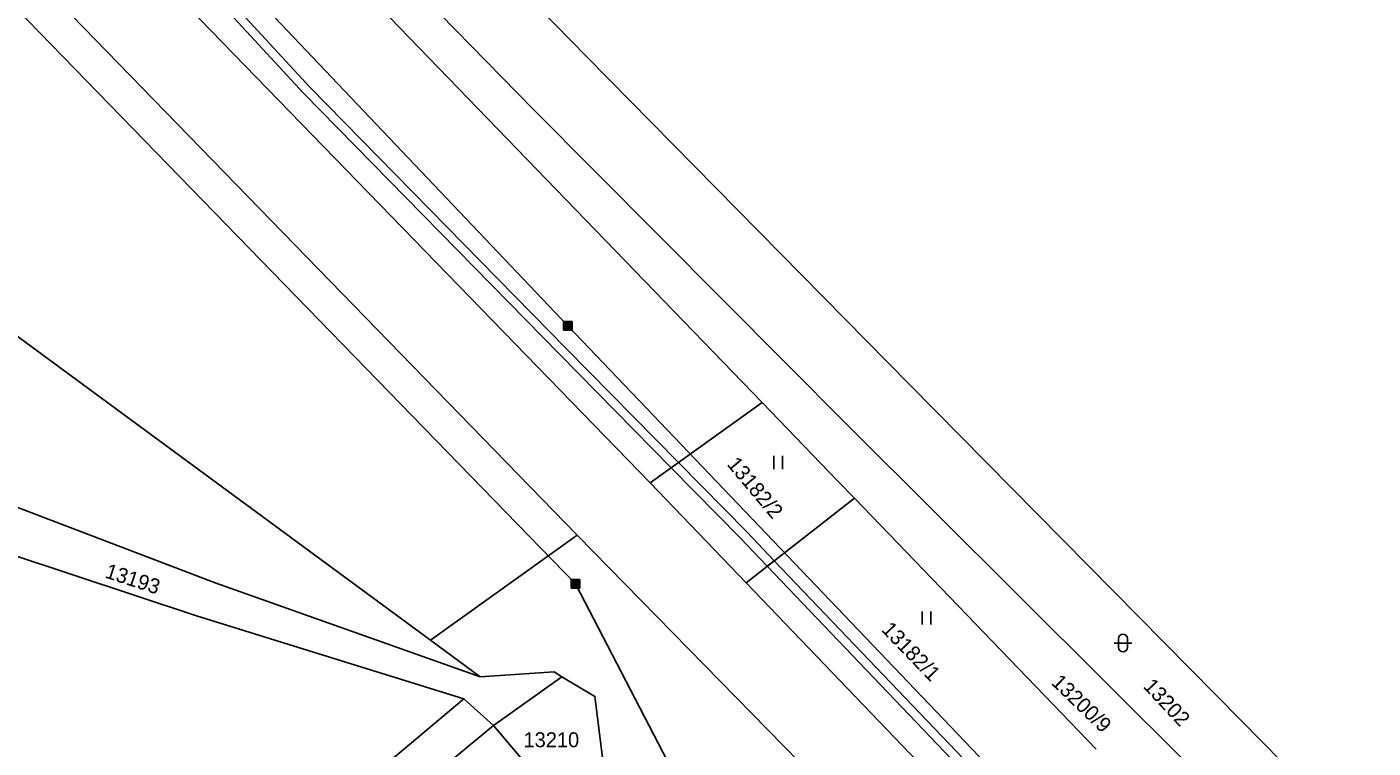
# Model space of a CAD drawing. Extents: x -821458 to -820266, y -1071458 to -1069826.
# Drawn here: x -820498 to -820345.1, y -1071152.4 to -1071070.4 of the extents above; entities that cross this region are included whole.
import ezdxf

# ---------------------------------------------------------------- set-up
doc = ezdxf.new("R2010")
doc.units = 0
for name, color, linetype in [('Vrstva 1', 7, 'Continuous'), ('Vrstva 13', 7, 'Continuous'), ('Vrstva 2', 7, 'Continuous'), ('Vrstva 3', 7, 'Continuous'), ('Vrstva 6', 7, 'Continuous')]:
    doc.layers.add(name, color=color, linetype=linetype)

msp = doc.modelspace()

# ---------------------------------------------------------------- linework, layer by layer
at = {"layer": 'Vrstva 1'}
for p, q in [((-820414.5, -1071113.1), (-820488.98, -1071036.1)), ((-820414.5, -1071113.1), (-820427.22, -1071122.22)), ((-820405.94, -1071121.99), (-820414.5, -1071113.1)), ((-820427.22, -1071122.22), (-820416.32, -1071133.58)), ((-820404.04, -1071123.96), (-820405.94, -1071121.99)), ((-820404.04, -1071123.96), (-820416.32, -1071133.58)), ((-820376.56, -1071152.47), (-820404.04, -1071123.96)), ((-820435.54, -1071128.19), (-820452.17, -1071140.11)), ((-820394.7, -1071169.8), (-820435.54, -1071128.19)), ((-820416.32, -1071133.58), (-820387.8, -1071163.3)), ((-820452.17, -1071140.11), (-820446.53, -1071144.26)), ((-820445.03, -1071149.78), (-820437.25, -1071144.25)), ((-820445.03, -1071149.78), (-820448.39, -1071146.76))]:
    msp.add_line(p, q, dxfattribs=at)
for points in [[(-820575.41, -1070898.25), (-820570.53, -1070910.66), (-820562.59, -1070929.03), (-820552.69, -1070946.67), (-820539.84, -1070967.11), (-820528.16, -1070983.62), (-820516.84, -1071000.47), (-820503.22, -1071015.12), (-820488.13, -1071031.13), (-820440.56, -1071079.73), (-820404.7, -1071115.79), (-820365.81, -1071154.53), (-820359.33, -1071162.29), (-820347, -1071174.7)], [(-820435.54, -1071128.19), (-820530.4, -1071030.6), (-820561.6, -1070981.6)], [(-820538.47, -1070998.6), (-820523.2, -1071023.4), (-820427.22, -1071122.22)], [(-820360.13, -1071149.18), (-820397.76, -1071111.06), (-820434.42, -1071073.84), (-820482, -1071025.25)], [(-820559.1, -1071106.03), (-820540.45, -1071075.18), (-820452.17, -1071140.11)], [(-820507.05, -1071122), (-820476.66, -1071133.59), (-820446.53, -1071144.26)], [(-820448.39, -1071146.76), (-820478.77, -1071137.34), (-820507.01, -1071128)], [(-820446.53, -1071144.26), (-820438.15, -1071143.71), (-820437.25, -1071144.25)], [(-820437.25, -1071144.25), (-820433.5, -1071146.49), (-820430.3, -1071172.18), (-820416.56, -1071192)], [(-820448.39, -1071146.76), (-820466.46, -1071161.95), (-820470.02, -1071165.17), (-820476.62, -1071174.38)], [(-820455.36, -1071177.84), (-820463.46, -1071171), (-820466.9, -1071167.9), (-820445.03, -1071149.78)], [(-820445.03, -1071149.78), (-820441.94, -1071153.46), (-820441.02, -1071157.59), (-820440.53, -1071158.71)], [(-820340.44, -1071169.52), (-820353.06, -1071156.4), (-820360.13, -1071149.18)]]:
    msp.add_lwpolyline(points, dxfattribs=at)
at = {"layer": 'Vrstva 13'}
for points in [[(-820530.72, -1071011.18), (-820529.96, -1071012.43), (-820528.27, -1071012.02), (-820526.68, -1071012.07), (-820522.93, -1071016.2), (-820522.95, -1071017.41), (-820509.47, -1071031.79), (-820489.32, -1071053.34), (-820466.63, -1071077.97), (-820437.5, -1071107.65), (-820424.84, -1071120.52), (-820424.02, -1071119.92), (-820436.78, -1071106.95), (-820465.91, -1071077.29), (-820488.58, -1071052.66), (-820508.75, -1071031.11), (-820521.95, -1071017.03), (-820521.93, -1071015.82), (-820526.22, -1071011.09), (-820528.37, -1071011.02), (-820530.28, -1071011.47)], [(-820424.84, -1071120.52), (-820416.99, -1071128.5), (-820413.93, -1071131.71), (-820413.14, -1071131.09), (-820416.27, -1071127.8), (-820424.02, -1071119.92)], [(-820413.93, -1071131.71), (-820385.75, -1071161.25), (-820385.03, -1071160.53), (-820413.14, -1071131.09)]]:
    msp.add_lwpolyline(points, close=True, dxfattribs=at)
at = {"layer": 'Vrstva 3'}
for p, q in [((-820413.19, -1071120.67), (-820413.19, -1071119.17)), ((-820412.19, -1071120.67), (-820412.19, -1071119.17)), ((-820396.35, -1071138.34), (-820396.35, -1071136.84)), ((-820395.35, -1071138.34), (-820395.35, -1071136.84)), ((-820374.53, -1071140.43), (-820372.53, -1071140.43)), ((-820374.03, -1071139.93), (-820374.03, -1071140.93)), ((-820373.03, -1071140.93), (-820373.03, -1071139.93))]:
    msp.add_line(p, q, dxfattribs=at)
for centre, start, end in [((-820373.53, -1071139.93), 0, 180), ((-820373.53, -1071140.93), 180, 359.9879)]:
    msp.add_arc(centre, 0.5, start, end, dxfattribs=at)
at = {"layer": 'Vrstva 6'}
for p, q in [((-820514.94, -1071021.94), (-820436.58, -1071104.39)), ((-820528.19, -1071038.53), (-820435.72, -1071133.7)), ((-820437.08, -1071103.89), (-820436.08, -1071103.89)), ((-820437.08, -1071104.89), (-820437.08, -1071103.89)), ((-820436.88, -1071104.89), (-820436.88, -1071103.89)), ((-820436.68, -1071104.89), (-820436.68, -1071103.89)), ((-820436.48, -1071104.89), (-820436.48, -1071103.89)), ((-820436.28, -1071104.89), (-820436.28, -1071103.89)), ((-820436.08, -1071104.89), (-820436.08, -1071103.89)), ((-820437.08, -1071104.09), (-820436.08, -1071104.09)), ((-820437.08, -1071104.29), (-820436.08, -1071104.29)), ((-820437.08, -1071104.49), (-820436.08, -1071104.49)), ((-820437.08, -1071104.69), (-820436.08, -1071104.69)), ((-820437.08, -1071104.89), (-820436.08, -1071104.89)), ((-820436.58, -1071104.39), (-820349.5, -1071195.59)), ((-820436.22, -1071133.2), (-820435.22, -1071133.2)), ((-820436.22, -1071134.2), (-820436.22, -1071133.2)), ((-820436.22, -1071133.4), (-820435.22, -1071133.4)), ((-820436.22, -1071133.6), (-820435.22, -1071133.6)), ((-820436.22, -1071133.8), (-820435.22, -1071133.8)), ((-820436.22, -1071134), (-820435.22, -1071134)), ((-820436.22, -1071134.2), (-820435.22, -1071134.2)), ((-820436.02, -1071134.2), (-820436.02, -1071133.2)), ((-820435.82, -1071134.2), (-820435.82, -1071133.2)), ((-820435.72, -1071133.7), (-820418.6, -1071166.69)), ((-820435.62, -1071134.2), (-820435.62, -1071133.2)), ((-820435.42, -1071134.2), (-820435.42, -1071133.2)), ((-820435.22, -1071134.2), (-820435.22, -1071133.2))]:
    msp.add_line(p, q, dxfattribs=at)

# ---------------------------------------------------------------- texts
at = {"layer": 'Vrstva 2'}
for s, rotation, p in [('13182/2', 310, (-820418.59, -1071120.16)), ('13193', 342, (-820489.26, -1071132.97)), ('13182/1', 314, (-820401.05, -1071139)), ('13200/9', 316, (-820381.77, -1071145.03)), ('13202', 313, (-820371.32, -1071145.42))]:
    msp.add_text(s, height=1.7, rotation=rotation, dxfattribs=at).set_placement(p)
msp.add_text('13210', height=1.7, dxfattribs=at).set_placement((-820441.62, -1071152.27))

doc.saveas('drawing.dxf')
